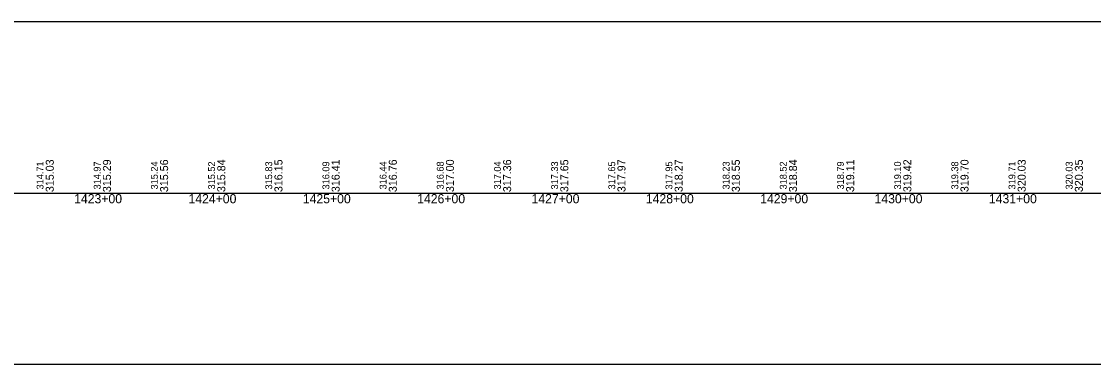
# Model space of a CAD drawing. Extents: x -3627 to 47473, y 2850 to 4350.
# Drawn here: x 29707 to 30645, y 2850 to 3150 of the extents above; entities that cross this region are included whole.
import ezdxf

# ---------------------------------------------------------------- set-up
doc = ezdxf.new("R2010")
doc.units = 0
for name, color, linetype in [('RD_DDB_StaTX', 7, 'Continuous'), ('RD_DDB_StripGrade', 7, 'Continuous'), ('RD_GPK_Profile_Cell', 7, 'Continuous'), ('RD_SHT_ShtClip', 7, 'Continuous')]:
    doc.layers.add(name, color=color, linetype=linetype)

msp = doc.modelspace()

# ---------------------------------------------------------------- linework, layer by layer
at = {"layer": 'RD_GPK_Profile_Cell'}
msp.add_line((1000, 3000), (46705.077602, 3000), dxfattribs=at)
at = {"layer": 'RD_SHT_ShtClip'}
msp.add_lwpolyline([(29433.33, 3150), (30973.33, 3150), (30973.33, 2850), (29433.33, 2850)], close=True, dxfattribs=at)

# ---------------------------------------------------------------- texts
at = {"layer": 'RD_DDB_StaTX'}
for s, p in [('1423+00', (29753.125471, 2991)), ('1424+00', (29853.125471, 2991)), ('1425+00', (29953.125471, 2991)), ('1426+00', (30053.125471, 2991)), ('1427+00', (30153.125471, 2991)), ('1428+00', (30253.125471, 2991)), ('1429+00', (30353.125471, 2991)), ('1430+00', (30453.125471, 2991)), ('1431+00', (30553.125471, 2991))]:
    msp.add_text(s, height=8, dxfattribs=at).set_placement(p)
at = {"layer": 'RD_DDB_StripGrade'}
for s, height, p in [('315.03', 7, (29735.33, 3000.75)), ('315.29', 7, (29785.33, 3000.75)), ('315.56', 7, (29835.33, 3000.75)), ('315.84', 7, (29885.33, 3000.75)), ('316.15', 7, (29935.33, 3000.75)), ('316.41', 7, (29985.33, 3000.75)), ('316.76', 7, (30035.33, 3000.75)), ('317.00', 7, (30085.33, 3000.75)), ('317.36', 7, (30135.33, 3000.75)), ('317.65', 7, (30185.33, 3000.75)), ('317.97', 7, (30235.33, 3000.75)), ('318.27', 7, (30285.33, 3000.75)), ('318.55', 7, (30335.33, 3000.75)), ('318.84', 7, (30385.33, 3000.75)), ('319.11', 7, (30435.33, 3000.75)), ('319.42', 7, (30485.33, 3000.75)), ('319.70', 7, (30535.33, 3000.75)), ('320.03', 7, (30585.33, 3000.75)), ('320.35', 7, (30635.33, 3000.75)), ('314.71', 6, (29726.33, 3003.073688)), ('314.97', 6, (29776.33, 3003.073688)), ('315.24', 6, (29826.33, 3003.073688)), ('315.52', 6, (29876.33, 3003.073688)), ('315.83', 6, (29926.33, 3003.073688)), ('316.09', 6, (29976.33, 3003.073688)), ('316.44', 6, (30026.33, 3003.073688)), ('316.68', 6, (30076.33, 3003.073688)), ('317.04', 6, (30126.33, 3003.073688)), ('317.33', 6, (30176.33, 3003.073688)), ('317.65', 6, (30226.33, 3003.073688)), ('317.95', 6, (30276.33, 3003.073688)), ('318.23', 6, (30326.33, 3003.073688)), ('318.52', 6, (30376.33, 3003.073688)), ('318.79', 6, (30426.33, 3003.073688)), ('319.10', 6, (30476.33, 3003.073688)), ('319.38', 6, (30526.33, 3003.073688)), ('319.71', 6, (30576.33, 3003.073688)), ('320.03', 6, (30626.33, 3003.073688))]:
    msp.add_text(s, height=height, rotation=90, dxfattribs=at).set_placement(p)

doc.saveas('drawing.dxf')
